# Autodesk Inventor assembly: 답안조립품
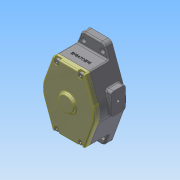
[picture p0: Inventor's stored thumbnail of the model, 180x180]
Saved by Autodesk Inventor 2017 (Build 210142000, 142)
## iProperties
Part Number: 답안조립품
Material: 일반
Document SubType Name: Assembly
Designer: Administrator
Author: Administrator
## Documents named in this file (14)
- C:\Users\Administrator\Desktop\20-김지훈\답안조립품.iam
- C:\Users\Administrator\Desktop\20-김지훈\본체.ipt
- C:\Users\Administrator\Desktop\20-김지훈\DU 부시.ipt
- C:\Users\Administrator\Desktop\20-김지훈\O링 G90.ipt
- C:\Users\Administrator\Desktop\20-김지훈\내접기어.ipt
- C:\Users\Administrator\Desktop\20-김지훈\스퍼기어.ipt
- C:\Users\Administrator\Desktop\20-김지훈\오일 실 14 25 4.ipt
- C:\Users\Administrator\Desktop\20-김지훈\오일레스 부시.ipt
- C:\Users\Administrator\Desktop\20-김지훈\육각 소켓 머리 볼트 M4 x 30.ipt
- C:\Users\Administrator\Desktop\20-김지훈\육각 소켓 머리 볼트 M6 x 12.ipt
- C:\Users\Administrator\Desktop\20-김지훈\축.ipt
- C:\Users\Administrator\Desktop\20-김지훈\커버.ipt
- C:\Users\Administrator\Desktop\20-김지훈\크레센트.ipt
- C:\Users\Administrator\Desktop\20-김지훈\평행 키 5x5x22.ipt
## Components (2 placed, 2 different names)
1. DU 부시:2
2. O링 G90:2
